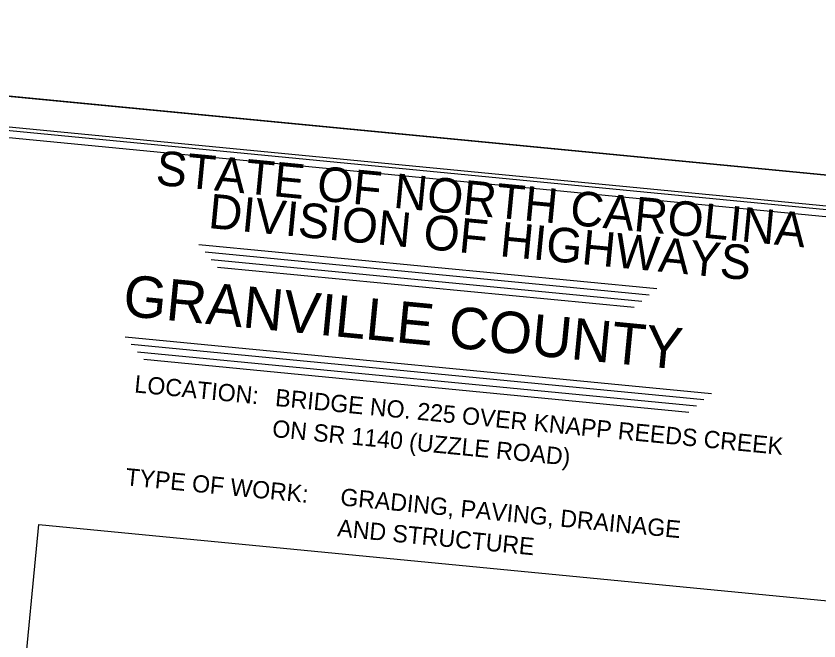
# Model space of a CAD drawing. Extents: x 2060574 to 2063008, y 912203 to 913082.
# Drawn here: x 2061000.5 to 2061348.8, y 912811 to 913082.2 of the extents above; entities that cross this region are included whole.
import ezdxf

# ---------------------------------------------------------------- set-up
doc = ezdxf.new("R2010")
doc.units = 0
for name, color, linetype in [('Sheet Cutting Line CELL', 7, 'Continuous'), ('Sheet Data Field CELL', 7, 'Continuous'), ('Sheet Plot Border Inside CELL', 7, 'Continuous'), ('Sheet Plot Border Outside CELL', 7, 'Continuous'), ('Sheet Title CELL', 7, 'Continuous')]:
    doc.layers.add(name, color=color, linetype=linetype)

msp = doc.modelspace()

# ---------------------------------------------------------------- linework, layer by layer
at = {"layer": 'Sheet Cutting Line CELL'}
msp.add_line((2060637.6, 913082.24), (2061643.31, 912985.03), dxfattribs=at)
at = {"layer": 'Sheet Data Field CELL'}
msp.add_lwpolyline([(2061010.39, 912861.5), (2061587.46, 912805.72), (2061558.93, 912510.54), (2060981.86, 912566.32)], close=True, dxfattribs=at)
at = {"layer": 'Sheet Plot Border Inside CELL'}
msp.add_lwpolyline([(2060583.16, 912437.96), (2061578.42, 912341.76), (2061639.33, 912971.88), (2060644.07, 913068.09)], close=True, dxfattribs=at)
at = {"layer": 'Sheet Plot Border Outside CELL'}
msp.add_lwpolyline([(2061643.31, 912985.03), (2060637.6, 913082.24), (2060574.1, 912425.31), (2061579.81, 912328.1)], close=True, dxfattribs=at)
at = {"layer": 'Sheet Title CELL'}
for p, q in [((2061079.75, 912983.11), (2061278.48, 912963.91)), ((2061082.45, 912979.84), (2061275.2, 912961.2)), ((2061085.15, 912976.56), (2061271.93, 912958.51)), ((2061087.85, 912973.29), (2061268.66, 912955.82)), ((2061047.76, 912943.05), (2061302.18, 912918.45)), ((2061050.46, 912939.78), (2061298.9, 912915.75)), ((2061053.16, 912936.49), (2061295.63, 912913.06)), ((2061055.85, 912933.23), (2061292.35, 912910.36))]:
    msp.add_line(p, q, dxfattribs=at)
for points in [[(2061625.75, 912971.65), (2060741.86, 913057.1)], [(2061622.47, 912968.96), (2060774.43, 913050.93)]]:
    msp.add_lwpolyline(points, dxfattribs=at)

# ---------------------------------------------------------------- texts
at = {"layer": 'Sheet Data Field CELL'}
for s, height, p in [('GRANVILLE COUNTY', 18, (2061046.4, 912952.16)), ('BRIDGE NO. 225 OVER KNAPP REEDS CREEK', 7.5001, (2061112.66, 912913)), ('ON SR 1140 (UZZLE ROAD)', 7.5001, (2061111.36, 912899.56)), ('GRADING, PAVING, DRAINAGE', 7.5001, (2061140.91, 912869.86)), ('AND STRUCTURE', 7.5001, (2061139.62, 912856.41))]:
    msp.add_text(s, height=height, rotation=354.4787, dxfattribs=at).set_placement(p)
at = {"layer": 'Sheet Title CELL'}
for s, height, p in [('STATE OF NORTH CAROLINA', 14.9999, (2061060.68, 913009.04)), ('DIVISION OF HIGHWAYS', 14.9999, (2061083.52, 912990.26)), ('LOCATION: ', 7.5, (2061051.58, 912918.9)), ('TYPE OF WORK:', 7.5001, (2061047.68, 912878.58))]:
    msp.add_text(s, height=height, rotation=354.4787, dxfattribs=at).set_placement(p)

doc.saveas('drawing.dxf')
